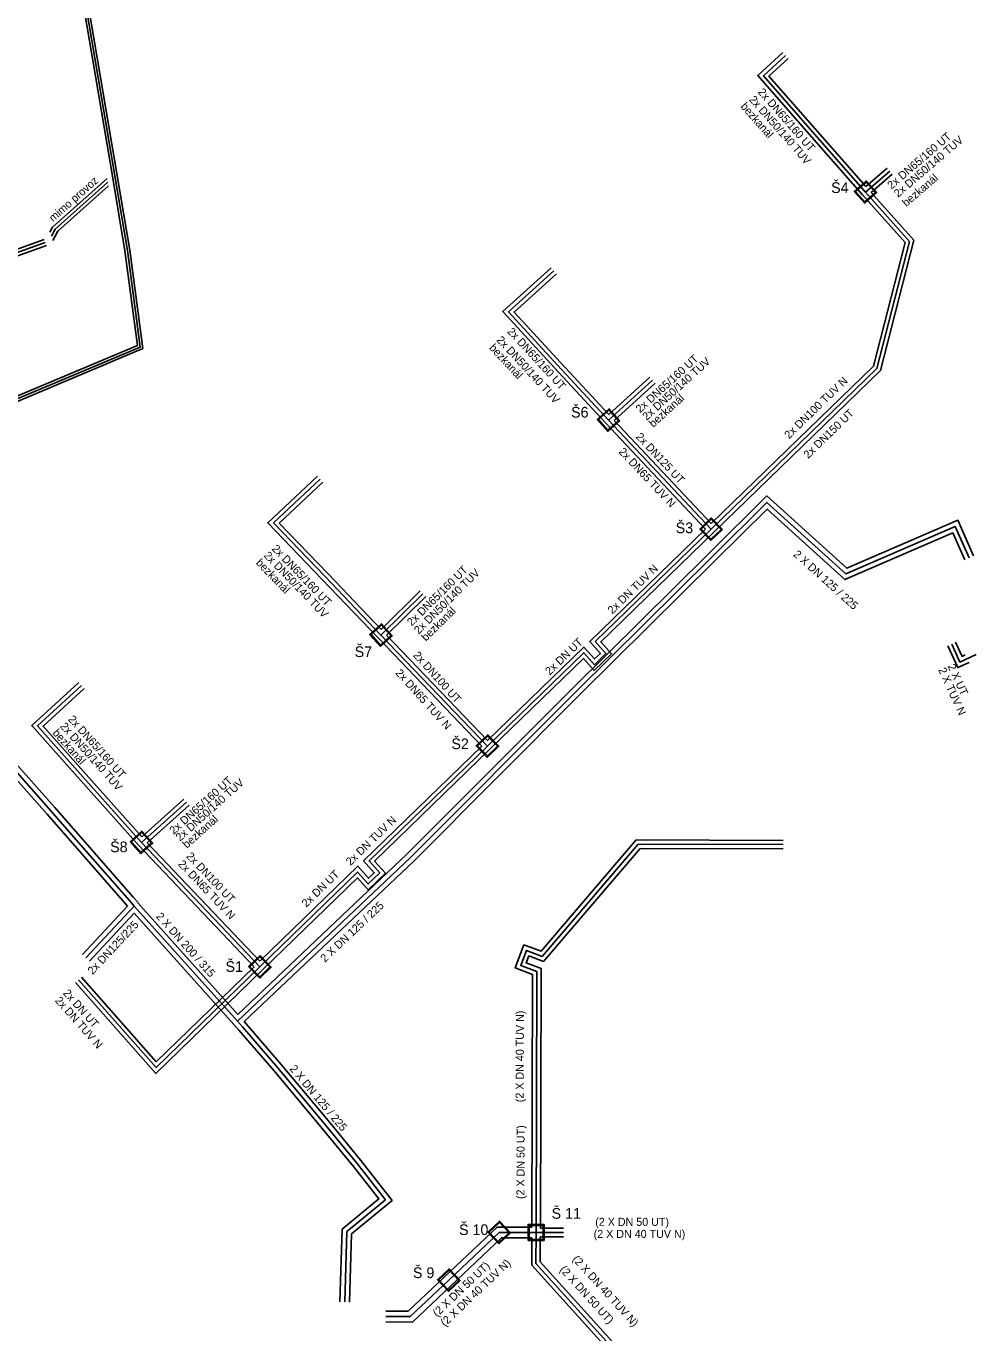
# Model space of a CAD drawing. Extents: x -606118 to -604472, y -1157869 to -1156854.
# Drawn here: x -605354.3 to -605176.4, y -1157710.9 to -1157466.1 of the extents above; entities that cross this region are included whole.
import ezdxf

# ---------------------------------------------------------------- set-up
doc = ezdxf.new("R2010")
doc.units = 0
for name, color, linetype in [('Osa trasy teplovodu', 7, 'Continuous'), ('označení šachty', 7, 'Continuous'), ('Teplovod - trasa - okraj', 7, 'Continuous'), ('Teplovod - trasa popis', 7, 'Continuous'), ('Teplovod - trasa popis 2', 7, 'Continuous'), ('Teplovod - trasa popis 3', 7, 'Continuous'), ('Šachta trasy teplovodu', 7, 'Continuous')]:
    doc.layers.add(name, color=color, linetype=linetype)

msp = doc.modelspace()

# ---------------------------------------------------------------- linework, layer by layer
at = {"layer": 'Osa trasy teplovodu'}
for p, q in [((-605196.94, -1157497.18), (-605192.4, -1157493.29)), ((-605245.12, -1157539.92), (-605236.86, -1157532.45)), ((-605225.86, -1157560.36), (-605245.12, -1157539.92)), ((-605287.76, -1157580.21), (-605279.89, -1157572.45)), ((-605267.78, -1157600.99), (-605287.76, -1157580.21)), ((-605332.66, -1157619.05), (-605324.23, -1157611.51)), ((-605310.45, -1157642.36), (-605332.66, -1157619.05)), ((-605333.99, -1157630.97), (-605343.06, -1157640.65)), ((-605333.99, -1157630.97), (-605314.67, -1157652.56)), ((-605258.49, -1157692.12), (-605253.52, -1157692.12))]:
    msp.add_line(p, q, dxfattribs=at)
for points in [[(-605337.6, -1157494.53), (-605346.28, -1157443.38), (-605349.14, -1157422.86), (-605349.42, -1157420.85), (-605351.18, -1157358)], [(-605196.94, -1157497.18), (-605205.58, -1157487.41), (-605216.08, -1157475.43), (-605211.91, -1157471.62)], [(-605385.3, -1157548.52), (-605378.11, -1157545.25), (-605355.5, -1157535.73), (-605332.89, -1157526.22), (-605335.29, -1157508.13), (-605337.6, -1157494.53)], [(-605349.52, -1157505.48), (-605348.84, -1157504.12), (-605338.94, -1157495.34)], [(-605225.86, -1157560.36), (-605194.78, -1157530.23), (-605188.69, -1157506.43), (-605196.94, -1157497.18)], [(-605430.37, -1157517.58), (-605424.17, -1157515.39), (-605423.54, -1157517.15), (-605408.37, -1157511.79), (-605407.18, -1157515.16), (-605394.93, -1157522.53), (-605350.67, -1157506.64)], [(-605245.12, -1157539.92), (-605254.65, -1157529.63), (-605263.87, -1157519.63), (-605255.32, -1157511.95)], [(-605287.76, -1157580.21), (-605298.21, -1157569.24), (-605307.89, -1157559.17), (-605299.15, -1157550.99)], [(-605396.88, -1157555.9), (-605388.35, -1157566.92), (-605381.14, -1157576.13), (-605373.4, -1157585.62), (-605367.05, -1157593.07), (-605357.39, -1157604.32), (-605349.62, -1157613.1), (-605343.11, -1157620.55), (-605334.92, -1157629.93), (-605333.99, -1157630.97)], [(-605177.52, -1157565.71), (-605180.1, -1157559.86), (-605200.6, -1157568.74), (-605215.41, -1157555.35), (-605225.75, -1157565.58), (-605251.05, -1157590.65), (-605282.25, -1157621.91), (-605314.65, -1157652.55)], [(-605267.78, -1157600.99), (-605249.75, -1157583.51), (-605247.74, -1157585.74), (-605245.58, -1157583.65), (-605247.59, -1157581.42), (-605225.86, -1157560.36)], [(-605180.76, -1157581.88), (-605179.24, -1157585.24), (-605176.16, -1157583.85)], [(-605332.66, -1157619.05), (-605343.56, -1157606.82), (-605352.15, -1157597.18), (-605343.89, -1157589.66)], [(-605310.45, -1157642.36), (-605292.14, -1157624.6), (-605290.13, -1157626.83), (-605287.97, -1157624.74), (-605289.98, -1157622.52), (-605267.78, -1157600.99)], [(-605258.69, -1157692.12), (-605258.55, -1157643.2), (-605261.55, -1157642.08), (-605260.5, -1157639.27), (-605257.51, -1157640.39), (-605239.53, -1157619.38), (-605212.34, -1157619.46)], [(-605344.46, -1157644.8), (-605329.92, -1157661.22), (-605310.45, -1157642.36)], [(-605314.67, -1157652.56), (-605313.71, -1157653.62), (-605307.11, -1157661.26), (-605298.06, -1157672.08), (-605292.21, -1157679.23), (-605286.92, -1157685.98), (-605294.16, -1157691.96), (-605294.54, -1157705.14)], [(-605286.86, -1157707.87), (-605282.27, -1157707.89), (-605275.04, -1157701.05), (-605265.61, -1157692.13), (-605265.59, -1157692.11), (-605258.69, -1157692.12)], [(-605258.69, -1157692.12), (-605258.7, -1157697.93), (-605243.66, -1157714.56), (-605230.34, -1157729.29), (-605226.44, -1157733.6), (-605210.63, -1157733.61)]]:
    msp.add_lwpolyline(points, dxfattribs=at)
at = {"layer": 'Teplovod - trasa - okraj'}
for p, q in [((-605196.86, -1157496.13), (-605192.89, -1157492.72)), ((-605191.91, -1157493.86), (-605195.87, -1157497.26)), ((-605245.07, -1157538.87), (-605237.36, -1157531.9)), ((-605236.35, -1157533.01), (-605244.05, -1157539.97)), ((-605226.92, -1157560.34), (-605245.67, -1157540.44)), ((-605244.05, -1157539.97), (-605225.84, -1157559.29)), ((-605287.74, -1157579.14), (-605280.41, -1157571.91)), ((-605279.36, -1157572.98), (-605286.7, -1157580.22)), ((-605286.7, -1157580.22), (-605267.76, -1157599.93)), ((-605268.84, -1157600.98), (-605288.3, -1157580.73)), ((-605332.6, -1157617.99), (-605324.73, -1157610.95)), ((-605323.73, -1157612.07), (-605331.58, -1157619.09)), ((-605311.51, -1157642.34), (-605333.2, -1157619.57)), ((-605331.58, -1157619.09), (-605310.43, -1157641.29)), ((-605335.24, -1157630.99), (-605343.71, -1157640.04)), ((-605333.32, -1157630.37), (-605314.61, -1157651.27)), ((-605334, -1157632.3), (-605342.4, -1157641.27)), ((-605334, -1157632.3), (-605315.34, -1157653.16)), ((-605257.89, -1157692.92), (-605253.52, -1157692.92)), ((-605257.88, -1157691.32), (-605253.52, -1157691.32))]:
    msp.add_line(p, q, dxfattribs=at)
for points in [[(-605338.04, -1157494.61), (-605346.72, -1157443.45), (-605349.87, -1157420.89), (-605351.63, -1157358.01)], [(-605350.72, -1157358.29), (-605348.97, -1157420.81), (-605345.83, -1157443.31), (-605337.15, -1157494.46)], [(-605197.5, -1157497.68), (-605206.14, -1157487.91), (-605217.13, -1157475.37), (-605212.42, -1157471.07)], [(-605211.4, -1157472.17), (-605215.03, -1157475.49), (-605205.02, -1157486.91), (-605196.86, -1157496.13)], [(-605385.5, -1157548.12), (-605378.29, -1157544.84), (-605355.68, -1157535.32), (-605333.39, -1157525.93), (-605335.74, -1157508.2), (-605338.04, -1157494.61)], [(-605337.15, -1157494.46), (-605334.84, -1157508.07), (-605332.4, -1157526.5), (-605355.33, -1157536.15), (-605377.93, -1157545.66), (-605385.09, -1157548.92)], [(-605349.8, -1157504.69), (-605349.32, -1157503.75), (-605339.07, -1157494.65)], [(-605338.82, -1157496.03), (-605348.35, -1157504.49), (-605349.24, -1157506.25)], [(-605225.84, -1157559.29), (-605195.46, -1157529.84), (-605189.51, -1157506.63), (-605197.5, -1157497.68)], [(-605195.87, -1157497.26), (-605187.86, -1157506.23), (-605194.11, -1157530.63), (-605225.34, -1157560.9)], [(-605430.57, -1157517.01), (-605423.8, -1157514.62), (-605423.18, -1157516.39), (-605408.01, -1157511.03), (-605406.69, -1157514.76), (-605394.87, -1157521.87), (-605350.87, -1157506.08)], [(-605350.46, -1157507.21), (-605395, -1157523.2), (-605407.68, -1157515.56), (-605408.74, -1157512.56), (-605423.91, -1157517.92), (-605424.53, -1157516.15), (-605430.17, -1157518.14)], [(-605245.67, -1157540.43), (-605255.2, -1157530.14), (-605264.94, -1157519.58), (-605255.83, -1157511.39)], [(-605254.82, -1157512.5), (-605262.81, -1157519.68), (-605254.1, -1157529.12), (-605245.07, -1157538.87)], [(-605288.3, -1157580.72), (-605298.75, -1157569.76), (-605308.96, -1157559.15), (-605299.67, -1157550.45)], [(-605298.64, -1157551.54), (-605306.82, -1157559.2), (-605297.67, -1157568.72), (-605287.74, -1157579.14)], [(-605395.83, -1157555.71), (-605387.6, -1157566.34), (-605380.4, -1157575.54), (-605372.67, -1157585.01), (-605366.32, -1157592.45), (-605356.68, -1157603.7), (-605348.91, -1157612.48), (-605342.4, -1157619.93), (-605334.21, -1157629.3), (-605333.28, -1157630.33)], [(-605176.69, -1157565.35), (-605179.63, -1157558.68), (-605200.43, -1157567.68), (-605215.44, -1157554.11), (-605226.39, -1157564.95), (-605251.69, -1157590.01), (-605282.88, -1157621.27), (-605314.61, -1157651.27)], [(-605335.24, -1157630.99), (-605335.63, -1157630.56), (-605343.83, -1157621.18), (-605350.34, -1157613.73), (-605358.11, -1157604.95), (-605367.77, -1157593.69), (-605374.13, -1157586.23), (-605381.88, -1157576.73), (-605389.1, -1157567.5), (-605397.63, -1157556.48)], [(-605178.34, -1157566.07), (-605180.56, -1157561.04), (-605200.78, -1157569.79), (-605215.38, -1157556.59), (-605225.12, -1157566.23), (-605250.42, -1157591.28), (-605281.62, -1157622.56), (-605313.4, -1157652.61)], [(-605267.76, -1157599.93), (-605249.71, -1157582.43), (-605247.7, -1157584.66), (-605246.62, -1157583.62), (-605248.63, -1157581.39), (-605226.92, -1157560.34)], [(-605225.34, -1157560.9), (-605246.55, -1157581.46), (-605244.54, -1157583.69), (-605247.77, -1157586.82), (-605249.78, -1157584.59), (-605267.26, -1157601.53)], [(-605181.49, -1157582.21), (-605179.63, -1157586.3), (-605177.51, -1157585.34)], [(-605180.03, -1157581.55), (-605178.84, -1157584.18), (-605178.27, -1157583.92)], [(-605333.22, -1157619.55), (-605344.12, -1157607.32), (-605353.2, -1157597.13), (-605344.39, -1157589.11)], [(-605343.38, -1157590.22), (-605351.1, -1157597.24), (-605343, -1157606.32), (-605332.6, -1157617.99)], [(-605310.43, -1157641.29), (-605292.1, -1157623.52), (-605290.09, -1157625.75), (-605289.01, -1157624.71), (-605291.02, -1157622.48), (-605268.84, -1157600.98)], [(-605267.26, -1157601.53), (-605288.94, -1157622.55), (-605286.93, -1157624.78), (-605290.16, -1157627.91), (-605292.18, -1157625.68), (-605309.93, -1157642.89)], [(-605259.48, -1157691.12), (-605259.35, -1157643.76), (-605262.58, -1157642.56), (-605260.97, -1157638.24), (-605257.75, -1157639.44), (-605239.9, -1157618.58), (-605212.34, -1157618.66)], [(-605257.88, -1157691.32), (-605257.75, -1157642.64), (-605260.52, -1157641.61), (-605260.03, -1157640.3), (-605257.26, -1157641.33), (-605239.16, -1157620.18), (-605212.34, -1157620.26)], [(-605309.93, -1157642.89), (-605329.96, -1157662.31), (-605345.02, -1157645.3)], [(-605343.9, -1157644.3), (-605329.88, -1157660.14), (-605311.51, -1157642.34)], [(-605315.34, -1157653.16), (-605314.39, -1157654.22), (-605307.8, -1157661.84), (-605298.75, -1157672.65), (-605292.92, -1157679.79), (-605288.17, -1157685.85), (-605295.05, -1157691.52), (-605295.44, -1157705.11)], [(-605313.4, -1157652.61), (-605306.43, -1157660.68), (-605297.36, -1157671.51), (-605291.51, -1157678.67), (-605285.67, -1157686.12), (-605293.27, -1157692.39), (-605293.64, -1157705.17)], [(-605286.86, -1157706.87), (-605282.66, -1157706.89), (-605265.99, -1157691.11), (-605259.48, -1157691.12)], [(-605257.89, -1157692.92), (-605257.9, -1157697.62), (-605226.08, -1157732.8), (-605210.62, -1157732.81)], [(-605286.87, -1157708.87), (-605281.87, -1157708.9), (-605265.19, -1157693.11), (-605259.49, -1157693.12)], [(-605259.49, -1157693.12), (-605259.5, -1157698.24), (-605226.8, -1157734.4), (-605210.63, -1157734.41)]]:
    msp.add_lwpolyline(points, dxfattribs=at)
at = {"layer": 'Šachta trasy teplovodu'}
for points in [[(-605199.06, -1157497.07), (-605196.82, -1157495.06), (-605194.81, -1157497.3), (-605197.05, -1157499.3), (-605199.06, -1157497.07)], [(-605197.03, -1157499.04), (-605195.08, -1157497.28), (-605196.83, -1157495.33), (-605198.79, -1157497.08), (-605197.03, -1157499.04)], [(-605247.24, -1157539.79), (-605244.99, -1157537.8), (-605243, -1157540.05), (-605245.24, -1157542.04), (-605247.24, -1157539.79)], [(-605245.23, -1157541.78), (-605243.26, -1157540.03), (-605245.01, -1157538.06), (-605246.97, -1157539.81), (-605245.23, -1157541.78)], [(-605225.9, -1157562.49), (-605227.99, -1157560.33), (-605225.83, -1157558.24), (-605223.74, -1157560.39), (-605225.9, -1157562.49)], [(-605224.01, -1157560.39), (-605225.84, -1157558.5), (-605227.73, -1157560.33), (-605225.9, -1157562.22), (-605224.01, -1157560.39)], [(-605289.88, -1157580.1), (-605287.64, -1157578.08), (-605285.63, -1157580.32), (-605287.86, -1157582.33), (-605289.88, -1157580.1)], [(-605287.85, -1157582.06), (-605285.9, -1157580.3), (-605287.66, -1157578.35), (-605289.61, -1157580.11), (-605287.85, -1157582.06)], [(-605267.82, -1157603.12), (-605269.91, -1157600.96), (-605267.75, -1157598.87), (-605265.66, -1157601.02), (-605267.82, -1157603.12)], [(-605265.92, -1157601.02), (-605267.76, -1157599.13), (-605269.64, -1157600.96), (-605267.81, -1157602.85), (-605265.92, -1157601.02)], [(-605334.78, -1157618.94), (-605332.55, -1157616.92), (-605330.54, -1157619.16), (-605332.77, -1157621.17), (-605334.78, -1157618.94)], [(-605332.76, -1157620.9), (-605330.8, -1157619.14), (-605332.56, -1157617.19), (-605334.52, -1157618.95), (-605332.76, -1157620.9)], [(-605310.49, -1157644.48), (-605312.58, -1157642.32), (-605310.42, -1157640.23), (-605308.33, -1157642.39), (-605310.49, -1157644.48)], [(-605308.6, -1157642.38), (-605310.43, -1157640.49), (-605312.31, -1157642.33), (-605310.48, -1157644.21), (-605308.6, -1157642.38)], [(-605265.67, -1157694.25), (-605267.74, -1157692.07), (-605265.56, -1157690), (-605263.49, -1157692.19), (-605265.67, -1157694.25)], [(-605263.75, -1157692.18), (-605265.56, -1157690.27), (-605267.47, -1157692.08), (-605265.66, -1157693.99), (-605263.75, -1157692.18)], [(-605260.19, -1157693.62), (-605260.19, -1157690.61), (-605257.18, -1157690.61), (-605257.18, -1157693.62), (-605260.19, -1157693.62)], [(-605257.37, -1157693.43), (-605257.37, -1157690.8), (-605260, -1157690.8), (-605260, -1157693.43), (-605257.37, -1157693.43)], [(-605275.1, -1157703.17), (-605277.16, -1157700.99), (-605274.98, -1157698.92), (-605272.91, -1157701.11), (-605275.1, -1157703.17)], [(-605273.18, -1157701.1), (-605274.99, -1157699.19), (-605276.9, -1157701), (-605275.09, -1157702.91), (-605273.18, -1157701.1)]]:
    msp.add_lwpolyline(points, dxfattribs=at)

# ---------------------------------------------------------------- texts
at = {"layer": 'označení šachty'}
for s, p in [('Š4', (-605203.37, -1157497.36)), ('Š6', (-605252.12, -1157539.44)), ('Š3', (-605232.51, -1157561.1)), ('Š7', (-605292.68, -1157584.31)), ('Š2', (-605274.55, -1157601.57)), ('Š8', (-605338.52, -1157620.87)), ('Š1', (-605316.89, -1157643.3)), ('Š 11', (-605255.77, -1157689.55)), ('Š 10', (-605273.12, -1157692.6)), ('Š 9', (-605281.76, -1157700.67))]:
    msp.add_text(s, height=2, dxfattribs=at).set_placement(p)
at = {"layer": 'Teplovod - trasa popis'}
for s, rotation, p in [('2x DN65/160 UT', 311.2368, (-605217.21, -1157478.52)), ('2x DN65/160 UT', 40.6292, (-605192.05, -1157496.73)), ('2x DN65/160 UT', 312.672, (-605264.19, -1157523.4)), ('2x DN65/160 UT', 42.1101, (-605239.18, -1157538.65)), ('2x DN150 UT', 44.1089, (-605207.68, -1157547.23)), ('2x DN125 UT', 313.2616, (-605240.11, -1157543.13)), ('2x DN65/160 UT', 313.8838, (-605308.32, -1157564.12)), ('2 X DN 125 / 225', 317.877, (-605210.57, -1157565.24)), ('2x DN65/160 UT', 44.5984, (-605281.99, -1157578.6)), ('2x DN UT', 44.1178, (-605256.11, -1157587.8)), ('2x DN100 UT', 312.0328, (-605281.82, -1157584.06)), ('2 X UT', 294.3857, (-605181.57, -1157586.01)), ('2x DN65/160 UT', 311.7283, (-605346.5, -1157596.05)), ('2x DN65/160 UT', 41.7956, (-605326.6, -1157617.64)), ('2x DN100 UT', 313.5389, (-605324.37, -1157621.73)), ('2x DN UT', 44.1178, (-605301.75, -1157631.3)), ('2 X DN 125 / 225', 43.3729, (-605298.26, -1157641.61)), ('2x DN125/225', 46.8679, (-605341.81, -1157643.92)), ('2 X DN 200 / 315', 311.8036, (-605330.03, -1157632.98)), ('2x DN UT', 311.5172, (-605347.44, -1157647.35)), ('2 X DN 125 / 225', 309.9129, (-605304.97, -1157661.5)), ('(2 X DN 50 UT)', 89.8398, (-605260.86, -1157685.86)), ('(2 X DN 50 UT)', 359.9894, (-605247.59, -1157690.88)), ('(2 X DN 50 UT)', 43.4302, (-605277.22, -1157708.03)), ('(2 X DN 50 UT)', 312.1474, (-605254.35, -1157699.15))]:
    msp.add_text(s, height=1.5, rotation=rotation, dxfattribs=at).set_placement(p)
at = {"layer": 'Teplovod - trasa popis 2'}
for s, rotation, p in [('2x DN50/140 TUV', 311.2368, (-605218.85, -1157479.93)), ('2x DN50/140 TUV', 40.6292, (-605190.82, -1157498.28)), ('mimo provoz', 41.5916, (-605349.19, -1157502.86)), ('2x DN50/140 TUV', 312.672, (-605266.2, -1157525)), ('2x DN50/140 TUV', 42.1101, (-605237.94, -1157540.06)), ('2x DN100 TUV N', 44.1178, (-605211.27, -1157543.52)), ('2x DN65 TUV N', 313.2616, (-605243.32, -1157545.94)), ('2x DN50/140 TUV', 313.8838, (-605309.83, -1157565.39)), ('2x DN50/140 TUV', 44.5984, (-605280.68, -1157580.11)), ('2x DN TUV N', 44.1178, (-605244.39, -1157576.36)), ('2x DN65 TUV N', 312.0328, (-605285.15, -1157587.36)), ('2 X TUV N', 294.3857, (-605183.34, -1157586.67)), ('2x DN50/140 TUV', 311.7283, (-605348, -1157597.35)), ('2x DN50/140 TUV', 41.7956, (-605325.42, -1157618.92)), ('2x DN TUV N', 44.1178, (-605293.46, -1157623.48)), ('2x DN65 TUV N', 313.5389, (-605325.91, -1157623.2)), ('2x DN TUV N', 311.5277, (-605348.96, -1157648.74)), ('(2 X DN 40 TUV N)', 89.8398, (-605261.01, -1157667.72)), ('(2 X DN 40 TUV N)', 359.9894, (-605247.88, -1157693.14)), ('(2 X DN 40 TUV N)', 43.4302, (-605275.75, -1157709.85)), ('(2 X DN 40 TUV N)', 312.1474, (-605251.97, -1157697.21))]:
    msp.add_text(s, height=1.5, rotation=rotation, dxfattribs=at).set_placement(p)
at = {"layer": 'Teplovod - trasa popis 3'}
for rotation, p in [(311.2368, (-605220.45, -1157481.21)), (40.6292, (-605189.27, -1157500.01)), (312.672, (-605267.57, -1157526.46)), (42.1101, (-605236.71, -1157541.39)), (313.8838, (-605311.29, -1157566.76)), (44.5984, (-605279.31, -1157581.45)), (311.7283, (-605349.42, -1157598.61)), (41.7956, (-605324.14, -1157620.25))]:
    msp.add_text('bezkanál', height=1.5, rotation=rotation, dxfattribs=at).set_placement(p)

doc.saveas('drawing.dxf')
